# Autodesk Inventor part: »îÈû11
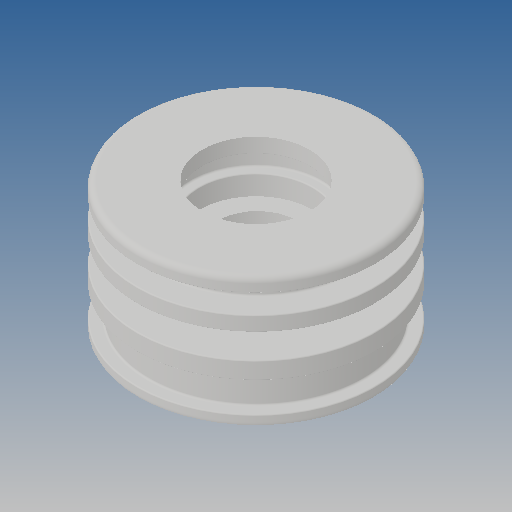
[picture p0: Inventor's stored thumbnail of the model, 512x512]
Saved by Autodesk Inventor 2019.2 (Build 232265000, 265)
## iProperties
Created: 2013-09
Part Number: »îÈû11
Material: Ogólny
Document SubType Name: Modeling
Designer: CADENGINEERING4
Density: 1 g/cm^3
Appearance: Domyślna
Author: CADENGINEERING4
Revision Number: ÈÎºÎ
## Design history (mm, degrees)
feature "µ¹½Ç1"
node "Bryła1"
